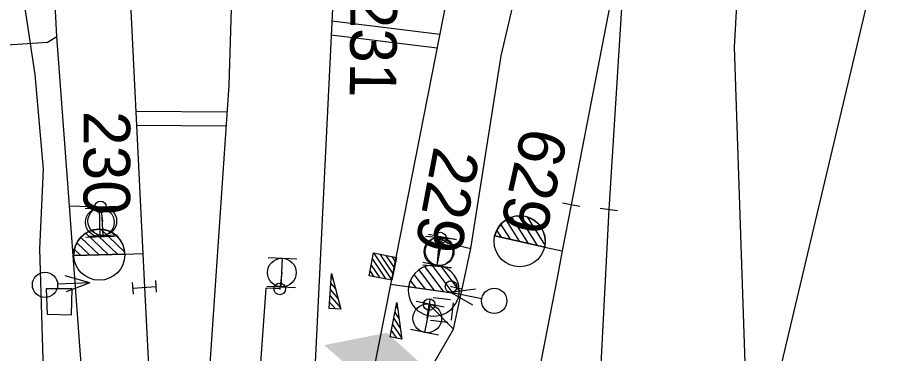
# Model space of a CAD drawing. Extents: x -545846 to -545044, y -1122650 to -1119108.
# Drawn here: x -545438.49 to -545401.32, y -1120328.93 to -1120314.49 of the extents above; entities that cross this region are included whole.
import ezdxf

# ---------------------------------------------------------------- set-up
doc = ezdxf.new("R2010")
doc.units = 0
for name, color, linetype in [('osvětlené plochy-hodnota-obrys', 7, 'Continuous'), ('Vrstva 1', 7, 'Continuous'), ('Vrstva 2', 7, 'Continuous'), ('Vrstva 26', 7, 'Continuous'), ('Vrstva 27', 7, 'Continuous'), ('Vrstva 28 - zabzar', 7, 'Continuous'), ('Vrstva 3', 7, 'Continuous'), ('Vrstva 3 - Lisy - Pocitaci body', 7, 'Continuous'), ('Vrstva 31', 7, 'Continuous'), ('Vrstva 35', 7, 'Continuous'), ('Vrstva 41', 7, 'Continuous'), ('Vrstva 47', 7, 'Continuous'), ('Vrstva 7', 7, 'Continuous')]:
    doc.layers.add(name, color=color, linetype=linetype)

msp = doc.modelspace()

# ---------------------------------------------------------------- linework, layer by layer
at = {"layer": 'osvětlené plochy-hodnota-obrys'}
msp.add_lwpolyline([(-545397.928, -1120102.854), (-545393.734, -1120124.857), (-545389.026, -1120196.694), (-545397.237, -1120293.846), (-545425.658, -1120413.558)], dxfattribs=at)
at = {"layer": 'Vrstva 1'}
for p, q in [((-545412.27, -1120309.99), (-545413.082, -1120322.742)), ((-545414.699, -1120322.537), (-545415.083, -1120324.521)), ((-545422.46, -1120325.954), (-545424.335, -1120335.396))]:
    msp.add_line(p, q, dxfattribs=at)
for points in [[(-545445.553, -1120198.39), (-545442.178, -1120215.766), (-545438.596, -1120234.052), (-545433.023, -1120262.752), (-545430.646, -1120277.904), (-545429.369, -1120293.55), (-545429.108, -1120307.546), (-545429.408, -1120317.397), (-545430.786, -1120337.552)], [(-545405.962, -1120286.281), (-545406.706, -1120298.136), (-545407.694, -1120315.774), (-545406.834, -1120341.201), (-545403.532, -1120362.869)], [(-545409.817, -1120297.315), (-545412.27, -1120309.99), (-545414.699, -1120322.537)], [(-545434.323, -1120299.853), (-545433.7, -1120312.441), (-545433.14, -1120323.79), (-545433.096, -1120324.633)], [(-545417.583, -1120301.153), (-545420.027, -1120313.584), (-545422.222, -1120324.733), (-545422.46, -1120325.954)], [(-545424.84, -1120311.521), (-545424.913, -1120313.24), (-545425.98, -1120335.133)], [(-545413.082, -1120322.742), (-545414.236, -1120345.141), (-545412.912, -1120364.705)], [(-545415.083, -1120324.521), (-545415.298, -1120325.67), (-545416.97, -1120334.276), (-545419.876, -1120349.295)], [(-545433.096, -1120324.633), (-545433.026, -1120326.082), (-545432.446, -1120337.526)]]:
    msp.add_lwpolyline(points, dxfattribs=at)
at = {"layer": 'Vrstva 2'}
for p, q in [((-545412.27, -1120309.99), (-545413.082, -1120322.742)), ((-545414.33, -1120322.605), (-545415.068, -1120322.469)), ((-545416.147, -1120324.281), (-545416.945, -1120323.012)), ((-545412.71, -1120322.792), (-545413.454, -1120322.692)), ((-545417.31, -1120324.015), (-545417.716, -1120323.371)), ((-545416.922, -1120324.104), (-545417.499, -1120323.187)), ((-545416.534, -1120324.193), (-545417.244, -1120323.065)), ((-545415.823, -1120324.268), (-545416.581, -1120323.062)), ((-545434.583, -1120324.675), (-545435.55, -1120323.759)), ((-545434.186, -1120324.664), (-545435.274, -1120323.634)), ((-545433.876, -1120324.571), (-545434.909, -1120323.591)), ((-545417.698, -1120323.927), (-545417.889, -1120323.624)), ((-545434.982, -1120324.685), (-545435.768, -1120323.94)), ((-545415.836, -1120324.352), (-545417.976, -1120323.864)), ((-545417.976, -1120323.864), (-545415.836, -1120324.351)), ((-545435.777, -1120324.706), (-545436.036, -1120324.461)), ((-545435.379, -1120324.696), (-545435.932, -1120324.172)), ((-545415.836, -1120324.351), (-545415.836, -1120324.352)), ((-545415.835, -1120324.352), (-545415.083, -1120324.521)), ((-545436.062, -1120324.714), (-545433.867, -1120324.655)), ((-545433.867, -1120324.656), (-545436.062, -1120324.714)), ((-545433.867, -1120324.656), (-545433.096, -1120324.633)), ((-545433.867, -1120324.655), (-545433.867, -1120324.656)), ((-545420.991, -1120325.196), (-545420.179, -1120326.281)), ((-545420.686, -1120325.128), (-545419.781, -1120326.339)), ((-545420.302, -1120325.166), (-545419.507, -1120326.229)), ((-545421.453, -1120325.529), (-545420.977, -1120326.165)), ((-545421.244, -1120325.333), (-545420.579, -1120326.224)), ((-545419.517, -1120326.37), (-545422.46, -1120325.954)), ((-545421.612, -1120325.794), (-545421.377, -1120326.108)), ((-545419.516, -1120326.377), (-545421.688, -1120326.063)), ((-545419.516, -1120326.376), (-545419.516, -1120326.377))]:
    msp.add_line(p, q, dxfattribs=at)
for points in [[(-545409.817, -1120297.315), (-545412.27, -1120309.99), (-545414.699, -1120322.537)], [(-545434.323, -1120299.853), (-545433.7, -1120312.441), (-545433.14, -1120323.79), (-545433.096, -1120324.633)], [(-545417.583, -1120301.153), (-545420.027, -1120313.584), (-545422.222, -1120324.733), (-545422.46, -1120325.954)], [(-545415.083, -1120324.521), (-545415.298, -1120325.67), (-545416.97, -1120334.276), (-545419.876, -1120349.295)]]:
    msp.add_lwpolyline(points, dxfattribs=at)
for centre in [(-545416.912, -1120324.105), (-545434.971, -1120324.684)]:
    msp.add_circle(centre, 1.097, dxfattribs=at)
for centre, radius, start, end in [((-545416.906, -1120324.108), 1.098, 347.1906, 167.1514), ((-545434.965, -1120324.685), 1.098, 1.5557, 181.5166), ((-545420.603, -1120326.22), 1.098, 351.8182, 171.7791), ((-545420.603, -1120326.221), 1.097, 171.7287, 352.1982)]:
    msp.add_arc(centre, radius, start, end, dxfattribs=at)
at = {"layer": 'Vrstva 26'}
msp.add_lwpolyline([(-545438.55, -1120303.48), (-545438.492, -1120305.085), (-545438.308, -1120313.144), (-545437.747, -1120316.944), (-545437.38, -1120321.007), (-545437.535, -1120324.422), (-545437.394, -1120329.162), (-545437.47, -1120335.028), (-545437.348, -1120345.435), (-545437.199, -1120348.43), (-545436.608, -1120350.182), (-545436.693, -1120361.871), (-545436.173, -1120369.258)], dxfattribs=at)
at = {"layer": 'Vrstva 27'}
for p, q in [((-545434.915, -1120322.605), (-545434.925, -1120322.655)), ((-545420.315, -1120323.945), (-545420.325, -1120323.995)), ((-545427.221, -1120326.125), (-545427.219, -1120326.175)), ((-545419.855, -1120326.025), (-545419.865, -1120326.075)), ((-545420.795, -1120326.795), (-545420.805, -1120326.845))]:
    msp.add_line(p, q, dxfattribs=at)
for centre in [(-545434.92, -1120322.63), (-545420.32, -1120323.97), (-545427.22, -1120326.15), (-545419.86, -1120326.05), (-545420.8, -1120326.82)]:
    msp.add_circle(centre, 0.25, dxfattribs=at)
at = {"layer": 'Vrstva 28 - zabzar'}
msp.add_line((-545419.86, -1120326.05), (-545419.38, -1120326.15), dxfattribs=at)
for points in [[(-545435.765, -1120369.178), (-545435.77, -1120368.34), (-545435.7, -1120360.44), (-545435.61, -1120354.31), (-545434.73, -1120342.05), (-545435.12, -1120337.81), (-545435.22, -1120336.54), (-545436.25, -1120322.58), (-545436.79, -1120315.32), (-545437.22, -1120307.02), (-545437.68, -1120303.89), (-545438.73, -1120300.14), (-545439.97, -1120292.07), (-545441.48, -1120282.7), (-545443.28, -1120271.83), (-545443.98, -1120270.84), (-545444.63, -1120268.7), (-545444.19, -1120267.53), (-545444.84, -1120264.46), (-545445.64, -1120260.36), (-545446.4, -1120259.21), (-545446.05, -1120258.16), (-545447.8, -1120248.31)], [(-545427.618, -1120367.583), (-545427.73, -1120366.73), (-545426.26, -1120362.1), (-545425.93, -1120358.75), (-545426.06, -1120358.16), (-545425.86, -1120356.01), (-545424.84, -1120349.39), (-545423.77, -1120344.77), (-545423.29, -1120343.78), (-545421.2, -1120332.61), (-545420.56, -1120329.27), (-545419.75, -1120327.88), (-545419.38, -1120326.15), (-545419.01, -1120324.41), (-545417.7, -1120316.15), (-545416.09, -1120309.25), (-545415.26, -1120304.49), (-545415.02, -1120303.93), (-545414.26, -1120300.9), (-545413.79, -1120299.25), (-545413.13, -1120297.33), (-545413.24, -1120296.36), (-545411.75, -1120288.1), (-545410.36, -1120282.42)], [(-545462.52, -1120319.84), (-545461.64, -1120319.5), (-545459.33, -1120319.07), (-545458.38, -1120318.91), (-545457.27, -1120318.43), (-545454.85, -1120317.95), (-545453.68, -1120317.85), (-545452.57, -1120317.41), (-545449.97, -1120316.91), (-545448.94, -1120316.7), (-545447.54, -1120316.64), (-545445.02, -1120316.08), (-545443.6, -1120315.94), (-545442.27, -1120315.7), (-545441.2, -1120315.8), (-545438.48, -1120315.64), (-545437.19, -1120315.56), (-545436.79, -1120315.32)], [(-545436.25, -1120322.58), (-545434.92, -1120322.63), (-545434.84, -1120323.24)], [(-545420.35, -1120324.53), (-545420.32, -1120323.97), (-545419.98, -1120324.19), (-545419.01, -1120324.41)], [(-545427.13, -1120325.45), (-545427.22, -1120326.15), (-545427.81, -1120326.12), (-545428.44, -1120334.96), (-545429.15, -1120342.21), (-545428.28, -1120342.6), (-545423.87, -1120343.25), (-545423.29, -1120343.78)], [(-545420.88, -1120327.41), (-545420.8, -1120326.82), (-545419.75, -1120327.88)]]:
    msp.add_lwpolyline(points, dxfattribs=at)
at = {"layer": 'Vrstva 3'}
for p, q in [((-545435.579, -1120322.691), (-545434.348, -1120322.658)), ((-545434.93, -1120323.906), (-545434.964, -1120322.674)), ((-545435.546, -1120323.922), (-545434.315, -1120323.889)), ((-545420.957, -1120323.885), (-545419.73, -1120323.998)), ((-545420.456, -1120325.168), (-545420.344, -1120323.942)), ((-545421.07, -1120325.112), (-545419.843, -1120325.225)), ((-545435.383, -1120325.882), (-545436.434, -1120325.588)), ((-545435.383, -1120325.882), (-545436.761, -1120325.95)), ((-545435.383, -1120325.882), (-545436.4, -1120326.278)), ((-545433.504, -1120326.372), (-545433.545, -1120325.874)), ((-545432.507, -1120326.29), (-545432.548, -1120325.792)), ((-545433.524, -1120326.123), (-545432.528, -1120326.041)), ((-545419.889, -1120326.288), (-545418.807, -1120326.151)), ((-545419.889, -1120326.288), (-545418.535, -1120326.557)), ((-545419.889, -1120326.288), (-545418.941, -1120326.828))]:
    msp.add_line(p, q, dxfattribs=at)
for centre, radius in [((-545434.948, -1120323.288), 0.616), ((-545420.4, -1120324.552), 0.616), ((-545437.303, -1120325.975), 0.542), ((-545418.004, -1120326.664), 0.542)]:
    msp.add_circle(centre, radius, dxfattribs=at)
at = {"layer": 'Vrstva 3 - Lisy - Pocitaci body'}
for p, q in [((-545435.485, -1120322.654), (-545434.254, -1120322.595)), ((-545434.81, -1120323.855), (-545434.87, -1120322.625)), ((-545435.426, -1120323.885), (-545434.195, -1120323.826)), ((-545419.627, -1120324.045), (-545420.835, -1120323.807)), ((-545420.231, -1120323.926), (-545420.469, -1120325.134)), ((-545427.715, -1120324.805), (-545426.485, -1120324.865)), ((-545427.16, -1120326.065), (-545427.1, -1120324.835)), ((-545423.236, -1120324.866), (-545422.657, -1120325.729)), ((-545423.185, -1120324.606), (-545422.397, -1120325.781)), ((-545422.925, -1120324.657), (-545422.345, -1120325.521)), ((-545422.664, -1120324.709), (-545422.294, -1120325.26)), ((-545422.404, -1120324.76), (-545422.243, -1120325)), ((-545423.287, -1120325.127), (-545422.917, -1120325.678)), ((-545419.865, -1120325.253), (-545421.073, -1120325.015)), ((-545423.338, -1120325.387), (-545423.177, -1120325.627)), ((-545425.022, -1120325.922), (-545424.821, -1120326.153)), ((-545425.003, -1120325.657), (-545424.925, -1120325.748)), ((-545427.775, -1120326.035), (-545426.545, -1120326.095)), ((-545425.041, -1120326.186), (-545424.717, -1120326.559)), ((-545425.079, -1120326.715), (-545424.828, -1120327.004)), ((-545425.06, -1120326.451), (-545424.613, -1120326.966)), ((-545420.156, -1120326.926), (-545421.364, -1120326.686)), ((-545425.097, -1120326.979), (-545425.092, -1120326.985)), ((-545422.219, -1120326.901), (-545422.152, -1120327)), ((-545420.76, -1120326.806), (-545421, -1120328.014)), ((-545422.319, -1120327.422), (-545422.041, -1120327.831)), ((-545422.269, -1120327.162), (-545422.097, -1120327.416)), ((-545422.369, -1120327.683), (-545421.986, -1120328.247)), ((-545422.469, -1120328.203), (-545422.464, -1120328.21)), ((-545422.419, -1120327.943), (-545422.204, -1120328.26)), ((-545420.396, -1120328.134), (-545421.604, -1120327.894))]:
    msp.add_line(p, q, dxfattribs=at)
msp.add_lwpolyline([(-545422.203, -1120324.799), (-545422.397, -1120325.781), (-545423.378, -1120325.587), (-545423.185, -1120324.606)], close=True, dxfattribs=at)
for points in [[(-545424.991, -1120325.489), (-545424.599, -1120327.02), (-545425.098, -1120326.985), (-545424.991, -1120325.489)], [(-545422.187, -1120326.735), (-545421.978, -1120328.303), (-545422.47, -1120328.209), (-545422.187, -1120326.735)]]:
    msp.add_lwpolyline(points, dxfattribs=at)
for centre in [(-545434.841, -1120323.238), (-545420.35, -1120324.533), (-545427.13, -1120325.448), (-545420.88, -1120327.413)]:
    msp.add_circle(centre, 0.616, dxfattribs=at)
at = {"layer": 'Vrstva 31'}
msp.add_lwpolyline([(-545427.618, -1120367.583), (-545427.73, -1120366.73), (-545426.26, -1120362.1), (-545425.93, -1120358.75), (-545425.86, -1120356.01), (-545424.84, -1120349.39), (-545423.77, -1120344.77), (-545423.29, -1120343.78), (-545423.25, -1120343.2), (-545421.2, -1120332.61), (-545420.56, -1120329.27), (-545419.75, -1120327.88), (-545419.01, -1120324.41), (-545417.7, -1120316.15), (-545416.09, -1120309.25), (-545415.02, -1120303.93), (-545414.26, -1120300.9), (-545413.13, -1120297.33), (-545413.24, -1120296.36), (-545411.75, -1120288.1), (-545410.36, -1120282.42)], dxfattribs=at)
at = {"layer": 'Vrstva 35'}
msp.add_lwpolyline([(-545442.27, -1120315.7), (-545441.2, -1120315.8), (-545438.48, -1120315.64), (-545437.19, -1120315.56)], dxfattribs=at)
at = {"layer": 'Vrstva 41'}
for p, q in [((-545420.853, -1120327.366), (-545420.763, -1120326.622)), ((-545420.624, -1120326.513), (-545419.88, -1120326.603)), ((-545419.771, -1120326.742), (-545419.861, -1120327.486)), ((-545420, -1120327.595), (-545420.744, -1120327.505))]:
    msp.add_line(p, q, dxfattribs=at)
at = {"layer": 'Vrstva 47'}
msp.add_lwpolyline([(-545436.142, -1120326.14), (-545437.254, -1120326.14), (-545437.205, -1120327.238), (-545436.169, -1120327.257)], close=True, dxfattribs=at)
at = {"layer": 'Vrstva 7'}
for p, q in [((-545424.981, -1120314.645), (-545420.347, -1120315.211)), ((-545425.011, -1120315.246), (-545420.463, -1120315.801)), ((-545429.488, -1120318.563), (-545433.4, -1120318.526)), ((-545429.529, -1120319.163), (-545433.37, -1120319.127))]:
    msp.add_line(p, q, dxfattribs=at)

# ---------------------------------------------------------------- texts
at = {"layer": 'osvětlené plochy-hodnota-obrys'}
msp.add_text('10', height=22.7812, rotation=281.0956, dxfattribs=at).set_placement((-545441.901, -1120328.829))
at = {"layer": 'Vrstva 2'}
for s, rotation, p in [('231', 269.5388, (-545424.177, -1120313.462)), ('230', 269.8952, (-545435.643, -1120318.506)), ('629', 257.3747, (-545416.78, -1120319.135)), ('229', 259.1856, (-545420.582, -1120319.983))]:
    msp.add_text(s, height=2, rotation=rotation, dxfattribs=at).set_placement(p)

doc.saveas('drawing.dxf')
